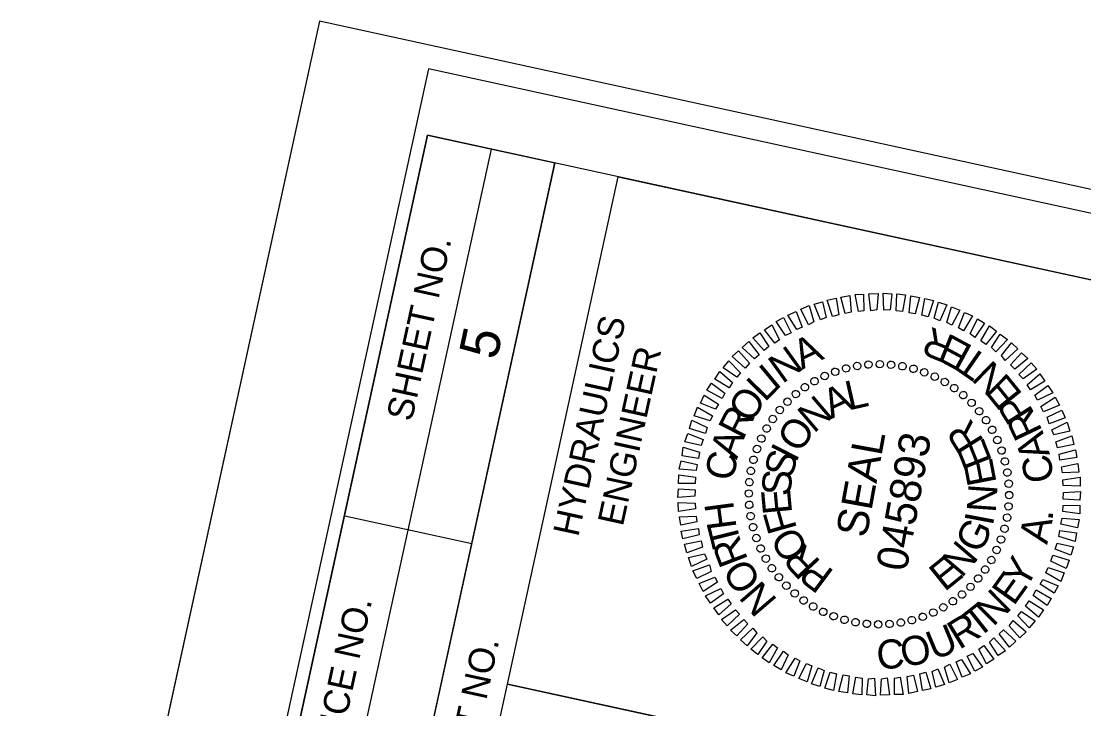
# Model space of a CAD drawing. Extents: x 1615716 to 1617263, y 900664 to 902742.
# Drawn here: x 1616130.6 to 1616335.1, y 902411.4 to 902543.8 of the extents above; entities that cross this region are included whole.
import ezdxf

# ---------------------------------------------------------------- set-up
doc = ezdxf.new("R2010")
doc.units = 0
for name, color, linetype in [('Default', 7, 'Continuous'), ('Prop EOT', 7, 'Continuous'), ('Prop SS Cut Line', 7, 'Continuous'), ('Prop SS Cut Text', 7, 'Continuous'), ('Prop SS Fill Line', 7, 'Continuous'), ('Prop SS Fill Text', 7, 'Continuous'), ('Prop SS Transition Line', 7, 'Continuous')]:
    doc.layers.add(name, color=color, linetype=linetype)

msp = doc.modelspace()

# ---------------------------------------------------------------- linework, layer by layer
at = {"layer": 'Default'}
for p, q in [((1616291.5, 902477.43), (1616291.5, 902477.43)), ((1616293.64, 902477.7), (1616293.64, 902477.7)), ((1616295.88, 902477.75), (1616295.88, 902477.75)), ((1616298.05, 902477.66), (1616298.05, 902477.66)), ((1616300.24, 902477.41), (1616300.24, 902477.41)), ((1616285.25, 902475.47), (1616285.25, 902475.47)), ((1616287.29, 902476.32), (1616287.29, 902476.32)), ((1616289.38, 902476.95), (1616289.38, 902476.95)), ((1616302.39, 902476.92), (1616302.39, 902476.92)), ((1616304.4, 902476.24), (1616304.4, 902476.24)), ((1616306.47, 902475.36), (1616306.47, 902475.36)), ((1616281.4, 902473.33), (1616281.4, 902473.33)), ((1616283.3, 902474.56), (1616283.3, 902474.56)), ((1616308.37, 902474.35), (1616308.37, 902474.35)), ((1616310.2, 902473.2), (1616310.2, 902473.2)), ((1616279.7, 902472.06), (1616279.7, 902472.06)), ((1616311.94, 902471.87), (1616311.94, 902471.87)), ((1616278.05, 902470.54), (1616278.05, 902470.54)), ((1616313.54, 902470.36), (1616313.54, 902470.36)), ((1616275.26, 902467.23), (1616275.26, 902467.23)), ((1616276.59, 902468.97), (1616276.59, 902468.97)), ((1616315.02, 902468.71), (1616315.02, 902468.71)), ((1616274.06, 902465.42), (1616274.06, 902465.42)), ((1616316.33, 902467), (1616316.33, 902467)), ((1616317.51, 902465.11), (1616317.51, 902465.11)), ((1616273.04, 902463.47), (1616273.04, 902463.47)), ((1616318.43, 902463.16), (1616318.43, 902463.16)), ((1616272.22, 902461.44), (1616272.22, 902461.44)), ((1616319.33, 902461.16), (1616319.33, 902461.16)), ((1616271.53, 902459.37), (1616271.53, 902459.37)), ((1616319.96, 902459.02), (1616319.96, 902459.02)), ((1616270.99, 902457.24), (1616270.99, 902457.24)), ((1616320.43, 902456.9), (1616320.43, 902456.9)), ((1616270.74, 902455.05), (1616270.74, 902455.05)), ((1616320.71, 902454.76), (1616320.71, 902454.76)), ((1616270.65, 902452.88), (1616270.65, 902452.88)), ((1616270.71, 902450.68), (1616270.71, 902450.68)), ((1616320.76, 902452.57), (1616320.76, 902452.57)), ((1616320.61, 902450.36), (1616320.61, 902450.36)), ((1616270.97, 902448.5), (1616270.97, 902448.5)), ((1616320.36, 902448.17), (1616320.36, 902448.17)), ((1616271.46, 902446.43), (1616271.46, 902446.43)), ((1616319.88, 902446.07), (1616319.88, 902446.07)), ((1616272.09, 902444.33), (1616272.09, 902444.33)), ((1616319.2, 902444.01), (1616319.2, 902444.01)), ((1616272.94, 902442.29), (1616272.94, 902442.29)), ((1616318.37, 902441.98), (1616318.37, 902441.98)), ((1616273.84, 902440.3), (1616273.84, 902440.3)), ((1616275.08, 902438.45), (1616275.08, 902438.45)), ((1616317.35, 902440.03), (1616317.35, 902440.03)), ((1616276.34, 902436.69), (1616276.34, 902436.69)), ((1616314.82, 902436.47), (1616314.82, 902436.47)), ((1616316.16, 902438.21), (1616316.16, 902438.21)), ((1616277.87, 902435.09), (1616277.87, 902435.09)), ((1616313.31, 902434.87), (1616313.31, 902434.87)), ((1616279.48, 902433.58), (1616279.48, 902433.58)), ((1616311.72, 902433.38), (1616311.72, 902433.38)), ((1616281.22, 902432.24), (1616281.22, 902432.24)), ((1616283.03, 902431.05), (1616283.03, 902431.05)), ((1616308.11, 902430.89), (1616308.11, 902430.89)), ((1616309.95, 902432.08), (1616309.95, 902432.08)), ((1616284.93, 902430.04), (1616284.93, 902430.04)), ((1616286.97, 902429.21), (1616286.97, 902429.21)), ((1616289.03, 902428.53), (1616289.03, 902428.53)), ((1616302.03, 902428.49), (1616302.03, 902428.49)), ((1616304.13, 902429.13), (1616304.13, 902429.13)), ((1616306.16, 902429.97), (1616306.16, 902429.97)), ((1616291.17, 902428.04), (1616291.17, 902428.04)), ((1616293.36, 902427.79), (1616293.36, 902427.79)), ((1616295.53, 902427.7), (1616295.53, 902427.7)), ((1616297.73, 902427.75), (1616297.73, 902427.75)), ((1616299.91, 902428.02), (1616299.91, 902428.02))]:
    msp.add_line(p, q, dxfattribs=at)
for points in [[(1616284.39, 902486.35), (1616283.16, 902489.37), (1616284.81, 902489.78), (1616285.48, 902486.76)], [(1616286.69, 902487), (1616285.69, 902490.13), (1616287.39, 902490.53), (1616287.92, 902487.29)], [(1616289.13, 902487.52), (1616288.34, 902490.72), (1616290.02, 902491.02), (1616290.3, 902487.82)], [(1616291.69, 902487.92), (1616291.08, 902491.23), (1616292.71, 902491.29), (1616292.74, 902488.08)], [(1616294.11, 902488.09), (1616293.69, 902491.36), (1616295.48, 902491.39), (1616295.26, 902488.23)], [(1616296.62, 902488.19), (1616296.46, 902491.47), (1616298.12, 902491.37), (1616297.8, 902488.23)], [(1616298.98, 902488.06), (1616299.08, 902491.35), (1616300.77, 902491.14), (1616300.18, 902487.94)], [(1616301.46, 902487.71), (1616301.8, 902490.95), (1616303.47, 902490.64), (1616302.64, 902487.49)], [(1616303.92, 902487.26), (1616304.51, 902490.46), (1616306.16, 902490.05), (1616305.13, 902486.94)], [(1616306.3, 902486.62), (1616307.12, 902489.72), (1616308.7, 902489.23), (1616307.38, 902486.17)], [(1616279.83, 902484.49), (1616278.1, 902487.25), (1616279.7, 902487.92), (1616280.87, 902484.91)], [(1616282.08, 902485.4), (1616280.64, 902488.36), (1616282.25, 902489.08), (1616283.15, 902485.97)], [(1616308.69, 902485.83), (1616309.59, 902488.82), (1616311.21, 902488.21), (1616309.71, 902485.29)], [(1616310.94, 902484.76), (1616312.09, 902487.75), (1616313.65, 902487.11), (1616311.91, 902484.22)], [(1616277.68, 902483.31), (1616275.84, 902485.98), (1616277.3, 902486.78), (1616278.74, 902483.83)], [(1616313.22, 902483.63), (1616314.61, 902486.53), (1616315.99, 902485.72), (1616314.11, 902482.96)], [(1616273.59, 902480.4), (1616271.35, 902482.84), (1616272.74, 902483.8), (1616274.45, 902481.21)], [(1616275.59, 902481.86), (1616273.62, 902484.41), (1616275.01, 902485.37), (1616276.52, 902482.5)], [(1616315.26, 902482.29), (1616316.91, 902485.19), (1616318.25, 902484.18), (1616316.21, 902481.61)], [(1616317.31, 902481), (1616319, 902483.54), (1616320.4, 902482.57), (1616318.13, 902480.19)], [(1616271.73, 902478.81), (1616269.34, 902481.02), (1616270.61, 902482.16), (1616272.59, 902479.61)], [(1616319.21, 902479.43), (1616321.14, 902481.93), (1616322.4, 902480.73), (1616319.96, 902478.53)], [(1616269.88, 902477.01), (1616267.39, 902479.24), (1616268.6, 902480.34), (1616270.71, 902477.97)], [(1616320.97, 902477.64), (1616323.08, 902480), (1616324.29, 902478.86), (1616321.79, 902476.83)], [(1616268.29, 902475.27), (1616265.67, 902477.07), (1616266.78, 902478.44), (1616269.01, 902476.15)], [(1616322.57, 902475.82), (1616324.96, 902478.08), (1616326.05, 902476.81), (1616323.38, 902474.96)], [(1616266.8, 902473.25), (1616264.06, 902474.92), (1616265.03, 902476.37), (1616267.49, 902474.24)], [(1616324.18, 902473.8), (1616326.61, 902475.95), (1616327.57, 902474.55), (1616324.83, 902472.87)], [(1616265.45, 902471.16), (1616262.55, 902472.81), (1616263.4, 902474.13), (1616266, 902472.23)], [(1616325.66, 902471.85), (1616328.18, 902473.68), (1616329.14, 902472.28), (1616326.18, 902470.84)], [(1616264.21, 902469.1), (1616261.28, 902470.29), (1616262.01, 902471.79), (1616264.74, 902470.07)], [(1616326.83, 902469.66), (1616329.6, 902471.44), (1616330.39, 902469.92), (1616327.35, 902468.6)], [(1616263.19, 902466.85), (1616260.07, 902467.82), (1616260.72, 902469.48), (1616263.63, 902467.83)], [(1616328.02, 902467.56), (1616330.82, 902468.93), (1616331.52, 902467.48), (1616328.41, 902466.32)], [(1616262.24, 902464.43), (1616259.16, 902465.4), (1616259.66, 902466.98), (1616262.6, 902465.58)], [(1616328.91, 902465.16), (1616331.86, 902466.6), (1616332.42, 902464.92), (1616329.34, 902464.17)], [(1616261.46, 902462.13), (1616258.29, 902462.81), (1616258.84, 902464.44), (1616261.83, 902463.28)], [(1616329.7, 902462.83), (1616332.76, 902464), (1616333.17, 902462.35), (1616330, 902461.71)], [(1616260.91, 902459.64), (1616257.75, 902460.16), (1616258, 902461.8), (1616261.12, 902460.82)], [(1616330.34, 902460.48), (1616333.48, 902461.27), (1616333.77, 902459.8), (1616330.48, 902459.28)], [(1616260.49, 902457.33), (1616257.23, 902457.57), (1616257.57, 902459.18), (1616260.69, 902458.46)], [(1616330.8, 902458), (1616333.92, 902458.65), (1616334.12, 902456.99), (1616330.95, 902456.86)], [(1616260.28, 902454.82), (1616257.08, 902454.8), (1616257.13, 902456.47), (1616260.35, 902456.03)], [(1616331.06, 902455.52), (1616334.36, 902456.03), (1616334.39, 902454.3), (1616331.12, 902454.44)], [(1616260.2, 902452.4), (1616256.94, 902452.13), (1616257.04, 902453.79), (1616260.31, 902453.6)], [(1616331.17, 902453.06), (1616334.46, 902453.27), (1616334.31, 902451.62), (1616331.14, 902451.79)], [(1616260.35, 902449.93), (1616257.06, 902449.41), (1616257.02, 902451.15), (1616260.3, 902451.01)], [(1616331.12, 902450.57), (1616334.29, 902450.66), (1616334.29, 902448.98), (1616331.06, 902449.42)], [(1616260.61, 902447.44), (1616257.49, 902446.79), (1616257.28, 902448.41), (1616260.46, 902448.54)], [(1616330.93, 902448.12), (1616334.19, 902447.88), (1616333.84, 902446.27), (1616330.66, 902446.95)], [(1616261.02, 902444.93), (1616257.92, 902444.12), (1616257.59, 902445.66), (1616260.89, 902446.17)], [(1616330.45, 902445.77), (1616333.66, 902445.28), (1616333.42, 902443.65), (1616330.28, 902444.58)], [(1616261.7, 902442.57), (1616258.65, 902441.45), (1616258.24, 902443.1), (1616261.41, 902443.74)], [(1616329.95, 902443.32), (1616333.07, 902442.59), (1616332.58, 902441.01), (1616329.59, 902442.16)], [(1616262.5, 902440.24), (1616259.55, 902438.84), (1616259, 902440.57), (1616262.08, 902441.28)], [(1616329.12, 902441.03), (1616332.25, 902440.05), (1616331.71, 902438.47), (1616328.76, 902439.87)], [(1616263.39, 902437.89), (1616260.6, 902436.52), (1616259.85, 902437.98), (1616263.01, 902439.13)], [(1616328.22, 902438.6), (1616331.29, 902437.58), (1616330.69, 902435.96), (1616327.79, 902437.61)], [(1616264.58, 902435.79), (1616261.82, 902434.01), (1616261.03, 902435.52), (1616264.06, 902436.8)], [(1616265.75, 902433.54), (1616263.24, 902431.77), (1616262.27, 902433.16), (1616265.23, 902434.6)], [(1616327.2, 902436.35), (1616330.13, 902435.1), (1616329.36, 902433.67), (1616326.68, 902435.43)], [(1616267.23, 902431.65), (1616264.81, 902429.5), (1616263.84, 902430.89), (1616266.58, 902432.53)], [(1616325.91, 902434.3), (1616328.81, 902432.65), (1616328.01, 902431.32), (1616325.36, 902433.23)], [(1616268.8, 902429.63), (1616266.45, 902427.37), (1616265.36, 902428.63), (1616268.04, 902430.48)], [(1616324.56, 902432.2), (1616327.35, 902430.47), (1616326.38, 902429.08), (1616323.88, 902431.21)], [(1616270.44, 902427.81), (1616268.29, 902425.46), (1616267.07, 902426.59), (1616269.63, 902428.62)], [(1616321.49, 902428.44), (1616323.98, 902426.21), (1616322.76, 902425.11), (1616320.69, 902427.42)], [(1616323.12, 902430.13), (1616325.75, 902428.38), (1616324.58, 902427.02), (1616322.36, 902429.3)], [(1616272.15, 902426.02), (1616270.27, 902423.52), (1616269.01, 902424.71), (1616271.4, 902426.92)], [(1616319.64, 902426.65), (1616322.03, 902424.43), (1616320.8, 902423.28), (1616318.78, 902425.84)], [(1616274.1, 902424.45), (1616272.36, 902421.87), (1616271.02, 902422.87), (1616273.28, 902425.26)], [(1616317.77, 902425.06), (1616320.01, 902422.57), (1616318.62, 902421.65), (1616316.96, 902424.24)], [(1616276.15, 902423.16), (1616274.51, 902420.3), (1616273.16, 902421.26), (1616275.21, 902423.84)], [(1616278.19, 902421.82), (1616276.8, 902418.92), (1616275.42, 902419.73), (1616277.3, 902422.49)], [(1616313.72, 902422.09), (1616315.58, 902419.46), (1616314.11, 902418.66), (1616312.61, 902421.58)], [(1616315.82, 902423.58), (1616317.79, 902420.99), (1616316.35, 902420.08), (1616314.88, 902422.89)], [(1616280.42, 902420.65), (1616279.27, 902417.71), (1616277.76, 902418.34), (1616279.5, 902421.17)], [(1616282.73, 902419.67), (1616281.82, 902416.63), (1616280.2, 902417.23), (1616281.7, 902420.16)], [(1616309.27, 902420), (1616310.77, 902417.09), (1616309.18, 902416.41), (1616308.25, 902419.43)], [(1616311.57, 902420.9), (1616313.26, 902418.16), (1616311.67, 902417.53), (1616310.53, 902420.48)], [(1616285.12, 902418.82), (1616284.3, 902415.72), (1616282.66, 902416.22), (1616283.98, 902419.29)], [(1616287.48, 902418.14), (1616286.9, 902414.94), (1616285.25, 902415.39), (1616286.27, 902418.46)], [(1616304.67, 902418.45), (1616305.67, 902415.27), (1616304.02, 902414.91), (1616303.5, 902418.16)], [(1616306.97, 902419.1), (1616308.25, 902416.07), (1616306.59, 902415.61), (1616305.92, 902418.63)], [(1616289.95, 902417.74), (1616289.61, 902414.5), (1616287.93, 902414.75), (1616288.77, 902417.95)], [(1616292.42, 902417.34), (1616292.34, 902414.1), (1616290.6, 902414.32), (1616291.23, 902417.5)], [(1616294.8, 902417.31), (1616295, 902413.92), (1616293.3, 902414.08), (1616293.62, 902417.22)], [(1616297.25, 902417.37), (1616297.67, 902414.09), (1616295.94, 902414.05), (1616296.16, 902417.21)], [(1616299.71, 902417.48), (1616300.33, 902414.16), (1616298.65, 902414.17), (1616298.62, 902417.32)], [(1616302.29, 902417.92), (1616303.08, 902414.73), (1616301.38, 902414.38), (1616301.11, 902417.63)]]:
    msp.add_lwpolyline(points, close=True, dxfattribs=at)
for centre, major_axis in [((1616289.32, 902476.98), (-0.182, 0.696)), ((1616291.46, 902477.44), (-0.121, 0.709)), ((1616293.63, 902477.71), (-0.058, 0.717)), ((1616295.81, 902477.79), (0.004, 0.719)), ((1616297.99, 902477.68), (0.067, 0.716)), ((1616300.16, 902477.38), (0.129, 0.708)), ((1616302.29, 902476.9), (0.19, 0.694)), ((1616283.26, 902474.51), (-0.356, 0.625)), ((1616285.21, 902475.51), (-0.3, 0.654)), ((1616287.23, 902476.33), (-0.242, 0.677)), ((1616304.37, 902476.23), (0.25, 0.674)), ((1616306.39, 902475.38), (0.308, 0.65)), ((1616281.41, 902473.35), (-0.409, 0.592)), ((1616308.32, 902474.36), (0.363, 0.621)), ((1616310.15, 902473.17), (0.416, 0.587)), ((1616278.05, 902470.56), (-0.505, 0.512)), ((1616279.67, 902472.03), (-0.459, 0.554)), ((1616311.88, 902471.83), (0.466, 0.548)), ((1616313.48, 902470.34), (0.512, 0.505)), ((1616276.56, 902468.96), (-0.548, 0.466)), ((1616314.95, 902468.72), (0.554, 0.459)), ((1616275.22, 902467.23), (-0.587, 0.416)), ((1616316.27, 902466.98), (0.592, 0.409)), ((1616274.04, 902465.4), (-0.621, 0.363)), ((1616317.43, 902465.13), (0.625, 0.356)), ((1616273.02, 902463.46), (-0.65, 0.308)), ((1616318.43, 902463.18), (0.654, 0.3)), ((1616272.17, 902461.45), (-0.674, 0.25)), ((1616319.25, 902461.16), (0.677, 0.242)), ((1616271.5, 902459.37), (-0.694, 0.19)), ((1616319.9, 902459.07), (0.696, 0.182)), ((1616271.01, 902457.24), (-0.708, 0.129)), ((1616320.36, 902456.93), (0.709, 0.121)), ((1616270.71, 902455.07), (-0.716, 0.067)), ((1616320.63, 902454.77), (0.717, 0.058)), ((1616270.6, 902452.89), (-0.719, 0.004)), ((1616320.71, 902452.58), (0.719, -0.004)), ((1616270.69, 902450.7), (-0.717, -0.058)), ((1616320.6, 902450.4), (0.716, -0.067)), ((1616270.96, 902448.54), (-0.709, -0.121)), ((1616320.31, 902448.23), (0.708, -0.129)), ((1616271.42, 902446.4), (-0.696, -0.182)), ((1616319.82, 902446.1), (0.694, -0.19)), ((1616272.06, 902444.31), (-0.677, -0.242)), ((1616319.15, 902444.02), (0.674, -0.25)), ((1616272.89, 902442.29), (-0.654, -0.3)), ((1616318.3, 902442.01), (0.65, -0.308)), ((1616273.88, 902440.34), (-0.625, -0.356)), ((1616317.28, 902440.07), (0.621, -0.363)), ((1616275.05, 902438.49), (-0.592, -0.409)), ((1616316.09, 902438.24), (0.587, -0.416)), ((1616276.37, 902436.75), (-0.554, -0.459)), ((1616314.75, 902436.51), (0.548, -0.466)), ((1616277.83, 902435.13), (-0.512, -0.505)), ((1616279.44, 902433.64), (-0.466, -0.548)), ((1616313.27, 902434.91), (0.505, -0.512)), ((1616281.16, 902432.3), (-0.416, -0.587)), ((1616309.9, 902432.12), (0.409, -0.592)), ((1616311.64, 902433.44), (0.459, -0.554)), ((1616283, 902431.11), (-0.363, -0.621)), ((1616284.93, 902430.09), (-0.308, -0.65)), ((1616306.11, 902429.96), (0.3, -0.654)), ((1616308.05, 902430.96), (0.356, -0.625)), ((1616286.94, 902429.24), (-0.25, -0.674)), ((1616289.02, 902428.57), (-0.19, -0.694)), ((1616291.16, 902428.09), (-0.129, -0.708)), ((1616293.32, 902427.79), (-0.067, -0.716)), ((1616295.5, 902427.68), (-0.004, -0.719)), ((1616297.69, 902427.76), (0.058, -0.717)), ((1616299.86, 902428.03), (0.121, -0.709)), ((1616301.99, 902428.49), (0.182, -0.696)), ((1616304.08, 902429.14), (0.242, -0.677))]:
    msp.add_ellipse(centre, major_axis=major_axis, ratio=0.999708, dxfattribs=at)
at = {"layer": 'Prop SS Cut Line'}
msp.add_line((1616187.99, 902543.84), (1615828.85, 900898.58), dxfattribs=at)
at = {"layer": 'Prop SS Cut Text'}
msp.add_lwpolyline([(1616208.96, 902534.66), (1615853.55, 900906.5), (1616884.38, 900681.48), (1617239.79, 902309.64)], close=True, dxfattribs=at)
at = {"layer": 'Prop SS Fill Line'}
for p, q in [((1616178.38, 902323.78), (1616221.05, 902519.22)), ((1616190.6, 902321.11), (1616233.26, 902516.56)), ((1616190.6, 902321.11), (1616233.26, 902516.56)), ((1616192.84, 902448.61), (1616217.27, 902443.28)), ((1616224.15, 902416.19), (1616334.01, 902392.21))]:
    msp.add_line(p, q, dxfattribs=at)
for points in [[(1616208.79, 902521.9), (1615888.89, 901056.41), (1616914.73, 900832.48), (1617234.63, 902297.97)], [(1616166.12, 902326.45), (1616208.79, 902521.9), (1616233.26, 902516.56), (1616190.6, 902321.11)], [(1616224.15, 902416.19), (1616245.47, 902513.89), (1616355.38, 902489.9), (1616334.06, 902392.2)], [(1616202.81, 902318.44), (1616224.15, 902416.19), (1616334.06, 902392.2), (1616312.72, 902294.45)]]:
    msp.add_lwpolyline(points, close=True, dxfattribs=at)
at = {"layer": 'Prop SS Fill Text'}
msp.add_lwpolyline([(1616187.99, 902543.84), (1615828.85, 900898.58), (1616903.54, 900663.99), (1617262.68, 902309.25)], close=True, dxfattribs=at)

# ---------------------------------------------------------------- texts
at = {"layer": 'Default'}
for s, height, rotation, p in [('R', 5.6, 158.2455, (1616310.54, 902483.07)), ('A', 5.6, 26.1529, (1616280.83, 902476.7)), ('E', 5.6, 151.5972, (1616313.95, 902481.15)), ('N', 5.6, 35.6982, (1616277.06, 902473.9)), ('T', 5.6, 145.1966, (1616317, 902478.94)), ('I', 5.6, 39.697, (1616275.63, 902472.55)), ('N', 5.6, 135.6513, (1616321.05, 902475.05)), ('E', 5.6, 129.003, (1616323.46, 902471.97)), ('L', 5.6, 45.6768, (1616273.68, 902470.35)), ('A', 5.6, 25.4853, (1616286.5, 902467.21)), ('L', 5.6, 12.8174, (1616289.9, 902468.88)), ('O', 5.6, 55.8906, (1616270.91, 902466.17)), ('N', 5.6, 40.4011, (1616283.09, 902464.35)), ('R', 5.6, 62.836, (1616269.47, 902463.07)), ('P', 5.6, 122.3547, (1616325.5, 902468.62)), ('R', 5.6, 115.4093, (1616327.2, 902464.91)), ('O', 5.6, 56.312, (1616280.39, 902460.45)), ('R', 5.6, 122.1021, (1616315.98, 902463)), ('A', 5.6, 107.3745, (1616328.59, 902460.39)), ('A', 5.6, 70.8709, (1616268.29, 902459.3)), ('SEAL', 5.992, 79.6486, (1616293.24, 902444.18)), ('045893', 5.994, 79.6486, (1616300.95, 902437.67)), ('E', 5.6, 111.4979, (1616317.52, 902459.09)), ('S', 5.6, 73.8351, (1616278.79, 902455.48)), ('I', 5.6, 62.973, (1616279.61, 902458.62)), ('C', 5.6, 79.5, (1616267.61, 902455.11)), ('E', 5.6, 100.8938, (1616318.32, 902454.97)), ('C', 5.6, 98.7453, (1616329.36, 902455.37)), ('S', 5.6, 84.6973, (1616278.58, 902452.24)), ('E', 5.6, 95.3015, (1616278.96, 902449.1)), ('N', 5.6, 85.9779, (1616318.12, 902449.08)), ('H', 5.6, 97.5754, (1616268.27, 902446.28)), ('F', 5.6, 105.7951, (1616279.91, 902446.11)), ('I', 5.6, 79.3169, (1616317.55, 902446.5)), ('.', 5.6, 85.4364, (1616329.06, 902447.55)), ('G', 5.6, 64.401, (1616315.2, 902441.1)), ('A', 5.6, 77.4015, (1616328.01, 902442.94)), ('T', 5.6, 103.976, (1616269.16, 902443.26)), ('R', 5.6, 110.9214, (1616270.51, 902440.12)), ('O', 5.6, 121.7059, (1616282.34, 902442.03)), ('R', 5.6, 132.7523, (1616284.64, 902439.67)), ('N', 5.6, 49.4852, (1616311.55, 902436.47)), ('E', 5.6, 38.881, (1616308.28, 902433.84)), ('Y', 5.6, 60.9851, (1616323.92, 902434.21)), ('O', 5.6, 121.1353, (1616273.15, 902435.85)), ('P', 5.6, 143.3565, (1616287.24, 902437.85)), ('E', 5.6, 54.3368, (1616321.58, 902431.07)), ('N', 5.6, 130.6806, (1616276.26, 902432.34)), ('N', 5.6, 44.7916, (1616317.63, 902427.08)), ('T', 5.6, 38.3909, (1616314.63, 902424.8)), ('R', 5.6, 31.4455, (1616311.11, 902422.72)), ('U', 5.6, 22.5316, (1616306.27, 902420.69)), ('C', 5.6, 3.6886, (1616295.35, 902419)), ('O', 5.6, 12.3178, (1616300.42, 902419.33))]:
    msp.add_text(s, height=height, rotation=rotation, dxfattribs=at).set_placement(p)
at = {"layer": 'Prop EOT'}
for s, p in [('UNLESS ALL SIGNATURES COMPLETED', (1616334.84, 902306)), ('DOCUMENT NOT CONSIDERED FINAL', (1616327.32, 902312.83))]:
    msp.add_text(s, height=5.5, rotation=77.6862, dxfattribs=at).set_placement(p)
at = {"layer": 'Prop SS Fill Line'}
for s, height, p in [('SHEET NO.', 5, (1616205.72, 902466.58)), ('HYDRAULICS', 5, (1616237.77, 902444.38)), ('ENGINEER', 5, (1616246.35, 902446.4)), ('PROJECT REFERENCE NO.', 5.0001, (1616179.36, 902346.29)), ('R/W SHEET NO.', 5.0001, (1616211.74, 902374.84))]:
    msp.add_text(s, height=height, rotation=77.6862, dxfattribs=at).set_placement(p)
at = {"layer": 'Prop SS Transition Line'}
msp.add_text('5', height=7.5, rotation=77.6862, dxfattribs=at).set_placement((1616222.07, 902478.42))

doc.saveas('drawing.dxf')
